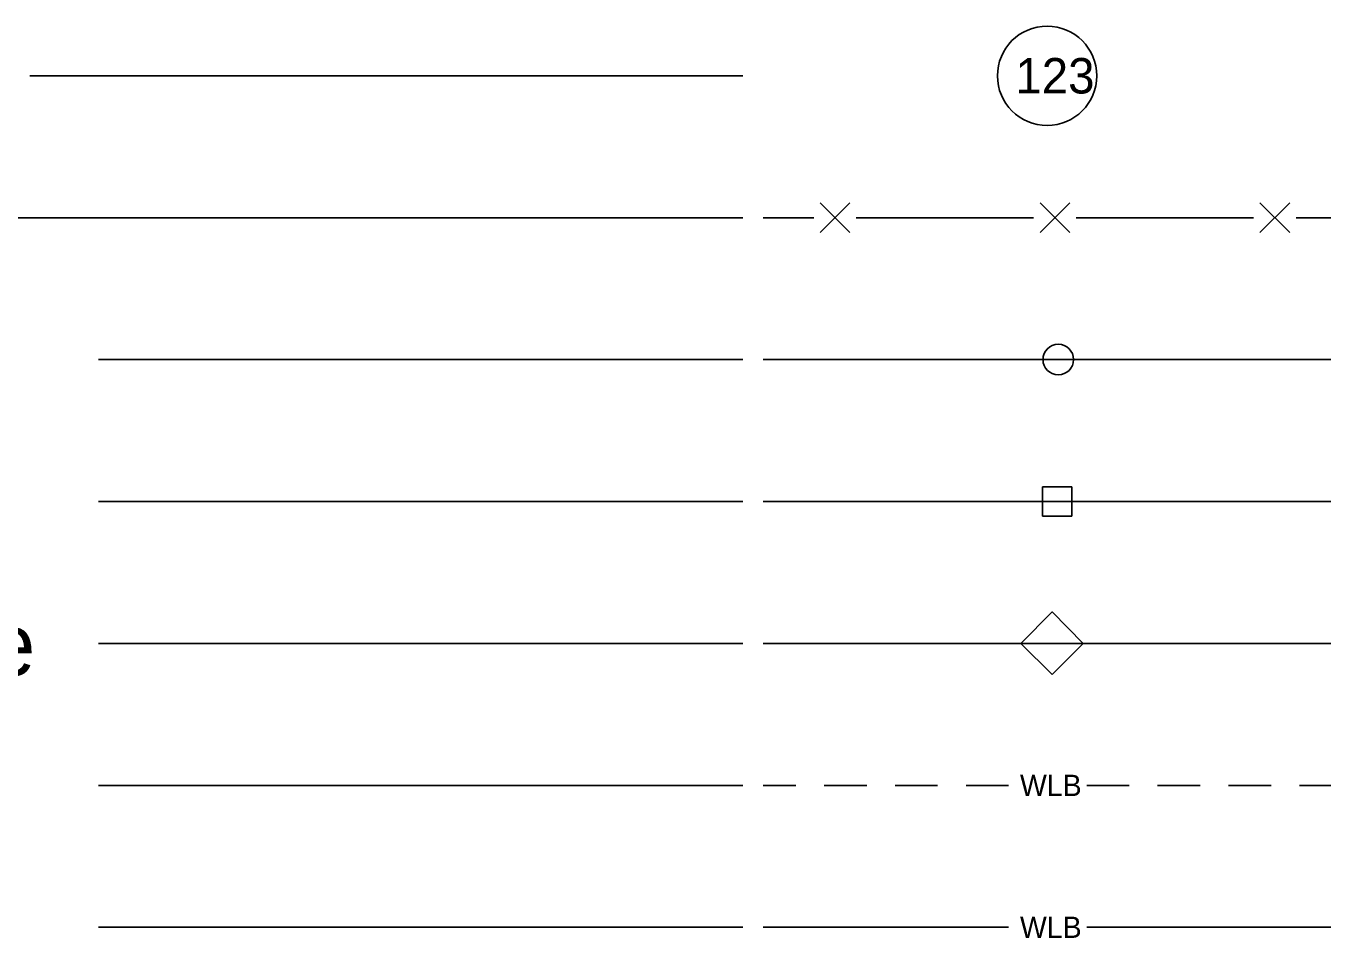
# Model space of a CAD drawing. Extents: x 754056.72 to 754059.56, y 596603.78 to 596605.61.
# Drawn here: x 754057.0827 to 754057.392, y 596604.926 to 596605.1421 of the extents above; entities that cross this region are included whole.
import ezdxf

# ---------------------------------------------------------------- set-up
doc = ezdxf.new("R2010")
doc.units = 0
doc.layers.add('Sheet_Symbology', color=7, linetype='Continuous')

msp = doc.modelspace()

# ---------------------------------------------------------------- linework, layer by layer
at = {"layer": 'Sheet_Symbology'}
for p, q in [((754057.25263, 596605.1303), (754057.08366, 596605.1303)), ((754057.27092, 596605.09314), (754057.27798, 596605.1002)), ((754057.27798, 596605.09314), (754057.27092, 596605.1002)), ((754057.32305, 596605.09314), (754057.33011, 596605.1002)), ((754057.33011, 596605.09314), (754057.32305, 596605.1002)), ((754057.37518, 596605.09314), (754057.38224, 596605.1002)), ((754057.38224, 596605.09314), (754057.37518, 596605.1002)), ((754057.25263, 596605.09667), (754057.00862, 596605.09667)), ((754057.25747, 596605.09667), (754057.26941, 596605.09667)), ((754057.2795, 596605.09667), (754057.30052, 596605.09667)), ((754057.30052, 596605.09667), (754057.32154, 596605.09667)), ((754057.33163, 596605.09667), (754057.35265, 596605.09667)), ((754057.35265, 596605.09667), (754057.37366, 596605.09667)), ((754057.38375, 596605.09667), (754057.39199, 596605.09667)), ((754057.25263, 596605.06304), (754057.09989, 596605.06304)), ((754057.25747, 596605.06304), (754057.39199, 596605.06304)), ((754057.25747, 596605.06304), (754057.39199, 596605.06304)), ((754057.25263, 596605.02941), (754057.09989, 596605.02941)), ((754057.25747, 596605.02941), (754057.39199, 596605.02941)), ((754057.25747, 596605.02941), (754057.39199, 596605.02941)), ((754057.25263, 596604.99578), (754057.09989, 596604.99578)), ((754057.25747, 596604.99578), (754057.39199, 596604.99578)), ((754057.25747, 596604.99578), (754057.39199, 596604.99578)), ((754057.25263, 596604.96214), (754057.09989, 596604.96214)), ((754057.25747, 596604.96214), (754057.26516, 596604.96214)), ((754057.27189, 596604.96214), (754057.28198, 596604.96214)), ((754057.2887, 596604.96214), (754057.29879, 596604.96214)), ((754057.30552, 596604.96214), (754057.31561, 596604.96214)), ((754057.33411, 596604.96214), (754057.3442, 596604.96214)), ((754057.35092, 596604.96214), (754057.36101, 596604.96214)), ((754057.36774, 596604.96214), (754057.37783, 596604.96214)), ((754057.38455, 596604.96214), (754057.39199, 596604.96214)), ((754057.25263, 596604.92851), (754057.09989, 596604.92851)), ((754057.25263, 596604.92851), (754057.09989, 596604.92851)), ((754057.25747, 596604.92851), (754057.31561, 596604.92851)), ((754057.33411, 596604.92851), (754057.39199, 596604.92851))]:
    msp.add_line(p, q, dxfattribs=at)
for points in [[(754057.32368, 596605.02596), (754057.33057, 596605.02596), (754057.33057, 596605.03285), (754057.32368, 596605.03285)], [(754057.32591, 596604.98838), (754057.33331, 596604.99578), (754057.32591, 596605.00326), (754057.31851, 596604.99578)]]:
    msp.add_lwpolyline(points, close=True, dxfattribs=at)
for centre, radius in [((754057.32473, 596605.1303), 0.01177), ((754057.32738, 596605.06304), 0.00362)]:
    msp.add_circle(centre, radius, dxfattribs=at)

# ---------------------------------------------------------------- texts
for s, height, p in [('123', 0.008408, (754057.31721, 596605.1261)), ('Proposed Barbed Wire Fence', 0.0147137, (754056.82573, 596604.98815)), ('WLB', 0.005045, (754057.3183, 596604.95962)), ('WLB', 0.005045, (754057.3183, 596604.92599))]:
    msp.add_text(s, height=height, dxfattribs=at).set_placement(p)

doc.saveas('drawing.dxf')
